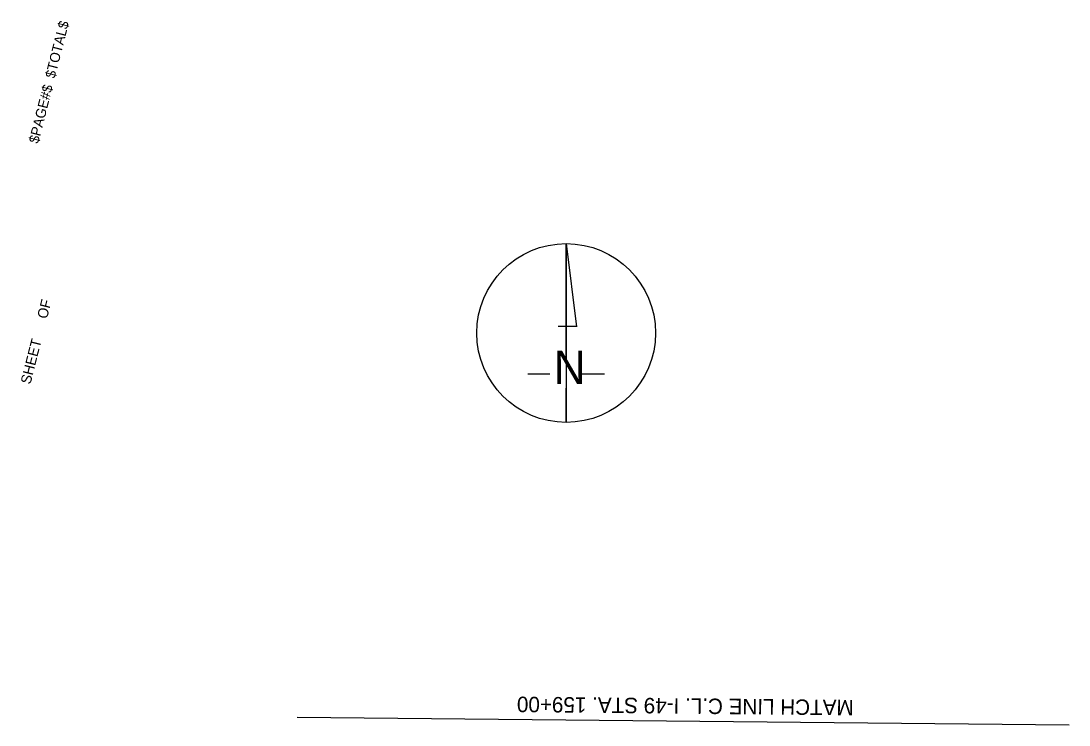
# Model space of a CAD drawing. Extents: x 631306 to 632723, y 370504 to 373810.
import ezdxf

# ---------------------------------------------------------------- set-up
doc = ezdxf.new("R2010")
doc.units = 0
for name, color, linetype in [('R_Border', 7, 'Continuous'), ('R_Border Notes', 7, 'Continuous'), ('R_Border_N Arrow', 7, 'Continuous'), ('R_No Plot', 7, 'Continuous')]:
    doc.layers.add(name, color=color, linetype=linetype)

msp = doc.modelspace()

# ---------------------------------------------------------------- linework, layer by layer
at = {"layer": 'R_Border'}
msp.add_line((632723.2, 372989), (631823.2, 372997.9), dxfattribs=at)
at = {"layer": 'R_Border_N Arrow'}
for p, q in [((632136.8, 373550.2), (632148.9, 373453.2)), ((632136.8, 373414.6), (632136.8, 373550.2)), ((632127.4, 373453.9), (632149, 373453.9)), ((632092.2, 373398.6), (632117.9, 373398.6)), ((632153.9, 373398.6), (632181.4, 373398.6)), ((632136.8, 373341.8), (632136.8, 373381.7))]:
    msp.add_line(p, q, dxfattribs=at)
at = {"layer": 'R_No Plot'}
msp.add_line((632136.8, 373550.2), (632136.8, 373341.8), dxfattribs=at)
msp.add_circle((632136.8, 373446), 104.2, dxfattribs=at)

# ---------------------------------------------------------------- texts
at = {"layer": 'R_Border'}
for s, p in [('$TOTAL$', (631540.5, 373742.2)), ('$PAGE#$', (631521.3, 373666.3))]:
    msp.add_text(s, height=11.72, rotation=75.7827, dxfattribs=at).set_placement(p)
at = {"layer": 'R_Border Notes'}
msp.add_text('MATCH LINE C.L. I-49 STA. 159+00', height=18, rotation=179.4304, dxfattribs=at).set_placement((632472.1, 373018.2))
at = {"layer": 'R_Border_N Arrow'}
msp.add_text('N', height=38.8, dxfattribs=at).set_placement((632122.1, 373386.6))
at = {"layer": 'R_No Plot'}
for s, p in [('OF', (631531.4, 373461.8)), ('SHEET', (631512.1, 373385.6))]:
    msp.add_text(s, height=12, rotation=75.7827, dxfattribs=at).set_placement(p)

doc.saveas('drawing.dxf')
